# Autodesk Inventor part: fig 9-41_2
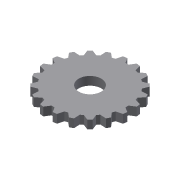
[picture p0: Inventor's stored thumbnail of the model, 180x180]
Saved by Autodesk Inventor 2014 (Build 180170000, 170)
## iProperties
Created: 2013-03
Part Number: fig 9-41_2
Material: Generic
Document SubType Name: Modeling
Designer: CADCIM
Density: 1 g/cm^3
Appearance: Default
Author: CADCIM
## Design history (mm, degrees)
sketch "Sketch1"
  geometry: C1 r 15 at (0, 0); C2 r 4 at (0, 0); 1 further point
  constraints: 2 centre point, 2 coincident
  dimensions: "d0" = 30 diameter of C1; "d2" = 8 diameter of C2
extrude "Extrusion1" new body sketch "Sketch1" distance "d3" = 3; taper "d4" = 0 deg
sketch "Sketch2"
  geometry: L1 (-1.675, 14.906)-(-0.536, 13.106); L2 (-0.536, 13.106)-(0.536, 13.106); L3 (0.536, 13.106)-(1.675, 14.906); L4 (0, 0)-(0, 16.254); C1 r 15 at (0, 0) reference; A1 r 15 centre (0, 0) between (1.675, 14.906) and (-1.675, 14.906); 2 further points
  constraints: 8 end point, 2 point on circle, 2 symmetric about line, 1 centre point, 1 coincident, 1 horizontal, 1 perpendicular
  dimensions: "d5" = 30 diameter of A1
extrude "Extrusion2" cut sketch "Sketch2" distance "d7" = 3; taper "d8" = 0 deg
body "Solid1"
pattern_circular "Circular Pattern1" dims angle "d10" = 360 deg
